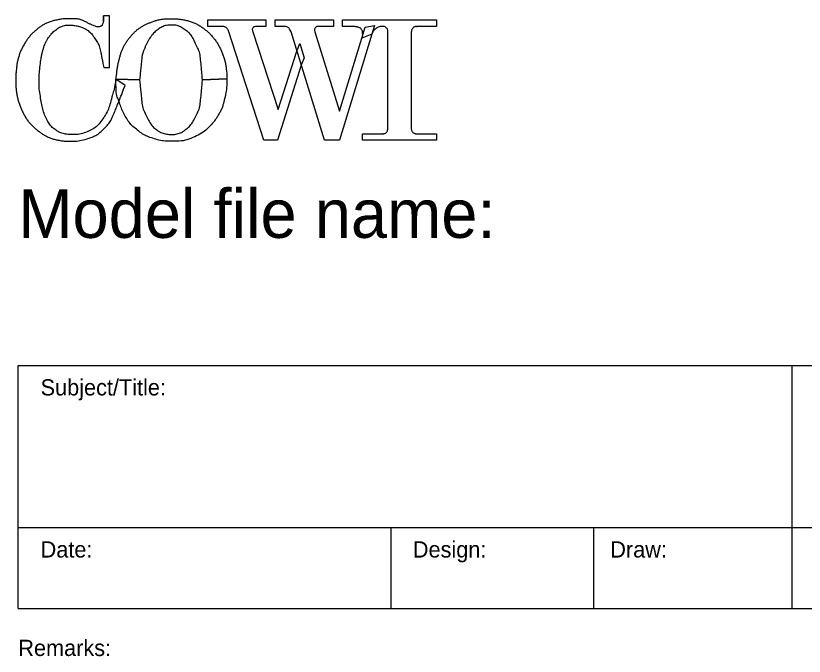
# Model space of a CAD drawing. Extents: x 0 to 511895, y 0 to 6211943.
# Drawn here: x -0.00016 to 0.04847, y -0.00294 to 0.03658 of the extents above; entities that cross this region are included whole.
import ezdxf

# ---------------------------------------------------------------- set-up
doc = ezdxf.new("R2010")
doc.units = 0
doc.layers.add('00_Modelskilt', color=7, linetype='Continuous')

msp = doc.modelspace()

# ---------------------------------------------------------------- linework, layer by layer
at = {"layer": '00_Modelskilt'}
for p, q in [((0.005244, 0.036576), (0.005244, 0.036326)), ((0.005624, 0.036576), (0.005244, 0.036576)), ((0.005244, 0.036576), (0.005244, 0.036226)), ((0.005244, 0.036226), (0.005244, 0.036576)), ((0.005244, 0.036576), (0.005244, 0.036326)), ((0.005624, 0.036576), (0.005244, 0.036576)), ((0.005244, 0.036576), (0.005244, 0.036226)), ((0.005244, 0.036226), (0.005244, 0.036576)), ((0.005624, 0.033376), (0.005624, 0.036576)), ((0.005624, 0.033376), (0.005624, 0.036576)), ((0.011694, 0.035916), (0.011694, 0.036326)), ((0.011694, 0.036326), (0.015274, 0.036326)), ((0.011694, 0.035916), (0.011694, 0.036326)), ((0.011694, 0.036326), (0.015274, 0.036326)), ((0.015274, 0.036326), (0.015274, 0.035916)), ((0.015274, 0.036326), (0.015274, 0.035916)), ((0.015834, 0.035916), (0.015834, 0.036326)), ((0.015834, 0.036326), (0.019434, 0.036326)), ((0.015834, 0.035916), (0.015834, 0.036326)), ((0.015834, 0.036326), (0.019434, 0.036326)), ((0.019434, 0.036326), (0.019434, 0.035916)), ((0.019434, 0.036326), (0.019434, 0.035916)), ((0.019994, 0.035916), (0.019994, 0.036326)), ((0.019994, 0.036326), (0.025784, 0.036326)), ((0.019994, 0.035916), (0.019994, 0.036326)), ((0.019994, 0.036326), (0.025784, 0.036326)), ((0.025784, 0.036326), (0.025784, 0.035916)), ((0.025784, 0.036326), (0.025784, 0.035916)), ((0.012504, 0.035916), (0.011694, 0.035916)), ((0.012504, 0.035916), (0.011694, 0.035916)), ((0.015144, 0.028906), (0.012994, 0.035586)), ((0.015144, 0.028906), (0.012994, 0.035586)), ((0.014464, 0.035586), (0.016034, 0.030786)), ((0.014464, 0.035586), (0.016034, 0.030786)), ((0.014714, 0.035916), (0.014634, 0.035906)), ((0.014714, 0.035916), (0.014634, 0.035906)), ((0.015274, 0.035916), (0.014714, 0.035916)), ((0.015274, 0.035916), (0.014714, 0.035916)), ((0.016344, 0.035916), (0.015834, 0.035916)), ((0.016344, 0.035916), (0.015834, 0.035916)), ((0.016384, 0.035916), (0.016344, 0.035916)), ((0.016384, 0.035916), (0.016344, 0.035916)), ((0.016824, 0.035586), (0.016774, 0.035686)), ((0.016824, 0.035586), (0.016774, 0.035686)), ((0.018874, 0.028906), (0.016824, 0.035586)), ((0.018874, 0.028906), (0.016824, 0.035586)), ((0.018274, 0.035696), (0.018294, 0.035586)), ((0.018274, 0.035696), (0.018294, 0.035586)), ((0.018294, 0.035586), (0.019814, 0.030686)), ((0.018294, 0.035586), (0.019814, 0.030686)), ((0.019434, 0.035916), (0.018574, 0.035916)), ((0.019434, 0.035916), (0.018574, 0.035916)), ((0.020654, 0.035916), (0.019994, 0.035916)), ((0.020654, 0.035916), (0.019994, 0.035916)), ((0.021194, 0.035186), (0.021394, 0.035866)), ((0.021194, 0.035186), (0.021394, 0.035866)), ((0.021394, 0.035866), (0.021964, 0.035966)), ((0.021394, 0.035866), (0.021964, 0.035966)), ((0.021964, 0.035966), (0.021794, 0.035436)), ((0.021964, 0.035966), (0.021794, 0.035436)), ((0.022784, 0.029696), (0.022784, 0.035536)), ((0.022784, 0.029696), (0.022784, 0.035536)), ((0.024234, 0.035536), (0.024234, 0.029696)), ((0.024234, 0.035536), (0.024234, 0.029696)), ((0.025784, 0.035916), (0.024564, 0.035906)), ((0.024564, 0.035906), (0.024594, 0.035916)), ((0.025784, 0.035916), (0.024564, 0.035906)), ((0.024564, 0.035906), (0.024594, 0.035916)), ((0.021794, 0.035436), (0.019814, 0.028906)), ((0.021794, 0.035436), (0.019814, 0.028906)), ((0.019814, 0.030686), (0.021194, 0.035186)), ((0.019814, 0.030686), (0.021194, 0.035186)), ((0.021794, 0.035436), (0.021194, 0.035186)), ((0.021794, 0.035436), (0.021194, 0.035186)), ((0.017174, 0.034396), (0.017364, 0.034866)), ((0.017174, 0.034396), (0.017364, 0.034866)), ((0.017364, 0.034866), (0.017624, 0.033976)), ((0.017364, 0.034866), (0.017624, 0.033976)), ((0.016034, 0.030786), (0.017174, 0.034396)), ((0.016034, 0.030786), (0.017174, 0.034396)), ((0.017624, 0.033976), (0.017454, 0.033526)), ((0.017624, 0.033976), (0.017454, 0.033526)), ((0.005274, 0.033376), (0.005624, 0.033376)), ((0.005274, 0.033376), (0.005624, 0.033376)), ((0.017454, 0.033526), (0.015984, 0.028906)), ((0.017454, 0.033526), (0.015984, 0.028906)), ((0.006584, 0.032266), (0.006014, 0.032656)), ((0.006014, 0.032656), (0.006014, 0.032616)), ((0.006044, 0.031866), (0.006014, 0.032656)), ((0.006014, 0.032656), (0.007484, 0.032616)), ((0.007484, 0.032616), (0.006014, 0.032656)), ((0.006014, 0.032656), (0.006014, 0.032616)), ((0.006584, 0.032266), (0.006014, 0.032656)), ((0.006014, 0.032656), (0.006014, 0.032616)), ((0.006044, 0.031866), (0.006014, 0.032656)), ((0.006014, 0.032656), (0.007484, 0.032616)), ((0.007484, 0.032616), (0.006014, 0.032656)), ((0.006014, 0.032656), (0.006014, 0.032616)), ((0.011364, 0.032616), (0.012864, 0.032676)), ((0.012864, 0.032676), (0.011364, 0.032616)), ((0.011364, 0.032616), (0.012864, 0.032676)), ((0.012864, 0.032676), (0.011364, 0.032616)), ((0.012864, 0.032676), (0.012864, 0.032616)), ((0.012864, 0.032676), (0.012864, 0.032616)), ((0.024234, 0.029696), (0.024234, 0.029606)), ((0.024234, 0.029696), (0.024234, 0.029606)), ((0.021234, 0.029286), (0.022474, 0.029296)), ((0.021234, 0.029286), (0.022474, 0.029296)), ((0.021234, 0.028906), (0.021234, 0.029286)), ((0.021234, 0.028906), (0.021234, 0.029286)), ((0.022474, 0.029296), (0.022454, 0.029286)), ((0.022474, 0.029296), (0.022454, 0.029286)), ((0.024594, 0.029286), (0.025784, 0.029286)), ((0.024594, 0.029286), (0.025784, 0.029286)), ((0.025784, 0.029286), (0.025784, 0.028906)), ((0.025784, 0.029286), (0.025784, 0.028906)), ((0.015984, 0.028906), (0.015144, 0.028906)), ((0.015984, 0.028906), (0.015144, 0.028906)), ((0.019814, 0.028906), (0.018874, 0.028906)), ((0.019814, 0.028906), (0.018874, 0.028906)), ((0.025784, 0.028906), (0.021234, 0.028906)), ((0.025784, 0.028906), (0.021234, 0.028906)), ((0, 0.015), (0.071, 0.015)), ((0, 0), (0, 0.015)), ((0.0477, 0.015), (0.0477, 0)), ((0, 0.005), (0.071, 0.005)), ((0.022975, 0.005), (0.022975, 0)), ((0.0355, 0), (0.0355, 0.005)), ((0, 0), (0.071, 0))]:
    msp.add_line(p, q, dxfattribs=at)
for points in [[(0.005244, 0.036326), (0.005244, 0.036232), (0.005233, 0.036139), (0.005194, 0.036046), (0.005166, 0.035982), (0.005108, 0.035939), (0.005044, 0.035916), (0.004963, 0.035888), (0.004872, 0.035888), (0.004794, 0.035916), (0.004683, 0.035956), (0.004573, 0.035999), (0.004464, 0.036046), (0.004281, 0.036125), (0.004117, 0.036224), (0.003924, 0.036296), (0.003691, 0.036384), (0.003451, 0.036395), (0.003214, 0.036396), (0.002954, 0.036398), (0.002693, 0.036375), (0.002434, 0.036326), (0.002195, 0.036281), (0.001968, 0.036218), (0.001744, 0.036116), (0.001539, 0.036023), (0.001359, 0.035906), (0.001184, 0.035766), (0.001007, 0.035626), (0.000848, 0.035479), (0.000704, 0.035306), (0.000557, 0.03513), (0.000435, 0.034946), (0.000324, 0.034746), (0.000211, 0.034543), (0.000113, 0.034338), (0.000044, 0.034116), (-0.000029, 0.033883), (-0.000077, 0.033648), (-0.000106, 0.033406), (-0.000138, 0.033143), (-0.000154, 0.03288), (-0.000156, 0.032616), (-0.000158, 0.032353), (-0.000145, 0.03209), (-0.000106, 0.031826), (-0.00007, 0.031583), (-0.000005, 0.03135), (0.000074, 0.031116), (0.000147, 0.030897), (0.000235, 0.03069), (0.000344, 0.030486), (0.000453, 0.030283), (0.000581, 0.0301), (0.000734, 0.029926), (0.000886, 0.029754), (0.001052, 0.029607), (0.001234, 0.029466), (0.001411, 0.02933), (0.00159, 0.029213), (0.001794, 0.029116), (0.002007, 0.029015), (0.002225, 0.028954), (0.002454, 0.028906), (0.002706, 0.028854), (0.002961, 0.028835), (0.003214, 0.028836), (0.003607, 0.028838), (0.003996, 0.028902), (0.004384, 0.029036), (0.004714, 0.02915), (0.004992, 0.029317), (0.005244, 0.029566), (0.005481, 0.029801), (0.005677, 0.030044), (0.005804, 0.030336), (0.005935, 0.030639), (0.006064, 0.03094), (0.006184, 0.031246), (0.006317, 0.031586), (0.006453, 0.031925), (0.006584, 0.032266)], [(0.005244, 0.036326), (0.005244, 0.036232), (0.005233, 0.036139), (0.005194, 0.036046), (0.005166, 0.035982), (0.005108, 0.035939), (0.005044, 0.035916), (0.004963, 0.035888), (0.004872, 0.035888), (0.004794, 0.035916), (0.004683, 0.035956), (0.004573, 0.035999), (0.004464, 0.036046), (0.004281, 0.036125), (0.004117, 0.036224), (0.003924, 0.036296), (0.003691, 0.036384), (0.003451, 0.036395), (0.003214, 0.036396), (0.002954, 0.036398), (0.002693, 0.036375), (0.002434, 0.036326), (0.002195, 0.036281), (0.001968, 0.036218), (0.001744, 0.036116), (0.001539, 0.036023), (0.001359, 0.035906), (0.001184, 0.035766), (0.001007, 0.035626), (0.000848, 0.035479), (0.000704, 0.035306), (0.000557, 0.03513), (0.000435, 0.034946), (0.000324, 0.034746), (0.000211, 0.034543), (0.000113, 0.034338), (0.000044, 0.034116), (-0.000029, 0.033883), (-0.000077, 0.033648), (-0.000106, 0.033406), (-0.000138, 0.033143), (-0.000154, 0.03288), (-0.000156, 0.032616), (-0.000158, 0.032353), (-0.000145, 0.03209), (-0.000106, 0.031826), (-0.00007, 0.031583), (-0.000005, 0.03135), (0.000074, 0.031116), (0.000147, 0.030897), (0.000235, 0.03069), (0.000344, 0.030486), (0.000453, 0.030283), (0.000581, 0.0301), (0.000734, 0.029926), (0.000886, 0.029754), (0.001052, 0.029607), (0.001234, 0.029466), (0.001411, 0.02933), (0.00159, 0.029213), (0.001794, 0.029116), (0.002007, 0.029015), (0.002225, 0.028954), (0.002454, 0.028906), (0.002706, 0.028854), (0.002961, 0.028835), (0.003214, 0.028836), (0.003607, 0.028838), (0.003996, 0.028902), (0.004384, 0.029036), (0.004714, 0.02915), (0.004992, 0.029317), (0.005244, 0.029566), (0.005481, 0.029801), (0.005677, 0.030044), (0.005804, 0.030336), (0.005935, 0.030639), (0.006064, 0.03094), (0.006184, 0.031246), (0.006317, 0.031586), (0.006453, 0.031925), (0.006584, 0.032266)], [(0.006014, 0.032616), (0.005936, 0.032136), (0.005806, 0.031668), (0.005674, 0.031196), (0.005566, 0.030811), (0.005387, 0.030467), (0.005144, 0.030126), (0.004931, 0.029828), (0.004674, 0.02962), (0.004334, 0.029466), (0.003962, 0.029298), (0.003589, 0.029235), (0.003214, 0.029246), (0.003064, 0.029251), (0.002914, 0.029274), (0.002764, 0.029316), (0.002617, 0.029358), (0.002484, 0.029407), (0.002354, 0.029496), (0.002082, 0.029684), (0.001884, 0.029914), (0.001744, 0.030206), (0.001577, 0.030556), (0.001476, 0.030905), (0.001414, 0.031276), (0.001339, 0.031723), (0.001274, 0.03217), (0.001284, 0.032616), (0.001294, 0.033066), (0.001341, 0.033516), (0.001414, 0.033966), (0.001446, 0.034164), (0.001487, 0.034355), (0.001544, 0.034546), (0.001593, 0.034714), (0.001662, 0.034871), (0.001744, 0.035026), (0.001822, 0.035175), (0.001915, 0.035308), (0.002024, 0.035436), (0.002122, 0.035552), (0.00223, 0.035646), (0.002354, 0.035736), (0.002482, 0.035829), (0.002613, 0.035898), (0.002764, 0.035946), (0.002912, 0.035994), (0.003065, 0.036005), (0.003214, 0.035996), (0.00349, 0.03598), (0.003764, 0.03593), (0.004034, 0.035816), (0.004155, 0.035765), (0.004255, 0.035701), (0.004354, 0.035616), (0.004463, 0.035523), (0.004553, 0.035424), (0.004634, 0.035306), (0.004809, 0.03505), (0.004982, 0.034793), (0.005044, 0.034496), (0.005121, 0.034123), (0.005196, 0.03375), (0.005274, 0.033376)], [(0.006014, 0.032616), (0.005936, 0.032136), (0.005806, 0.031668), (0.005674, 0.031196), (0.005566, 0.030811), (0.005387, 0.030467), (0.005144, 0.030126), (0.004931, 0.029828), (0.004674, 0.02962), (0.004334, 0.029466), (0.003962, 0.029298), (0.003589, 0.029235), (0.003214, 0.029246), (0.003064, 0.029251), (0.002914, 0.029274), (0.002764, 0.029316), (0.002617, 0.029358), (0.002484, 0.029407), (0.002354, 0.029496), (0.002082, 0.029684), (0.001884, 0.029914), (0.001744, 0.030206), (0.001577, 0.030556), (0.001476, 0.030905), (0.001414, 0.031276), (0.001339, 0.031723), (0.001274, 0.03217), (0.001284, 0.032616), (0.001294, 0.033066), (0.001341, 0.033516), (0.001414, 0.033966), (0.001446, 0.034164), (0.001487, 0.034355), (0.001544, 0.034546), (0.001593, 0.034714), (0.001662, 0.034871), (0.001744, 0.035026), (0.001822, 0.035175), (0.001915, 0.035308), (0.002024, 0.035436), (0.002122, 0.035552), (0.00223, 0.035646), (0.002354, 0.035736), (0.002482, 0.035829), (0.002613, 0.035898), (0.002764, 0.035946), (0.002912, 0.035994), (0.003065, 0.036005), (0.003214, 0.035996), (0.00349, 0.03598), (0.003764, 0.03593), (0.004034, 0.035816), (0.004155, 0.035765), (0.004255, 0.035701), (0.004354, 0.035616), (0.004463, 0.035523), (0.004553, 0.035424), (0.004634, 0.035306), (0.004809, 0.03505), (0.004982, 0.034793), (0.005044, 0.034496), (0.005121, 0.034123), (0.005196, 0.03375), (0.005274, 0.033376)], [(0.006014, 0.032616), (0.006054, 0.032869), (0.006076, 0.033123), (0.006114, 0.033376), (0.006147, 0.0336), (0.006205, 0.033817), (0.006264, 0.034036), (0.006315, 0.034229), (0.006379, 0.034415), (0.006464, 0.034596), (0.006553, 0.034787), (0.006669, 0.034957), (0.006794, 0.035126), (0.00691, 0.035284), (0.007032, 0.03543), (0.007174, 0.035566), (0.007314, 0.035702), (0.007465, 0.035817), (0.007634, 0.035916), (0.007805, 0.036017), (0.007979, 0.036096), (0.008164, 0.036166), (0.008364, 0.036243), (0.008563, 0.036307), (0.008774, 0.036346), (0.008994, 0.036388), (0.009214, 0.036398), (0.009434, 0.036396), (0.009687, 0.036394), (0.009941, 0.036371), (0.010194, 0.036326), (0.010433, 0.036284), (0.010659, 0.036216), (0.010884, 0.036116), (0.011094, 0.036023), (0.011282, 0.035907), (0.011464, 0.035766), (0.011644, 0.035627), (0.011804, 0.035478), (0.011954, 0.035306), (0.012107, 0.035131), (0.01224, 0.034949), (0.012354, 0.034746), (0.012468, 0.034543), (0.012559, 0.034336), (0.012634, 0.034116), (0.012713, 0.033883), (0.012782, 0.03365), (0.012814, 0.033406), (0.012845, 0.033163), (0.012867, 0.03292), (0.012864, 0.032676)], [(0.006014, 0.032616), (0.006054, 0.032869), (0.006076, 0.033123), (0.006114, 0.033376), (0.006147, 0.0336), (0.006205, 0.033817), (0.006264, 0.034036), (0.006315, 0.034229), (0.006379, 0.034415), (0.006464, 0.034596), (0.006553, 0.034787), (0.006669, 0.034957), (0.006794, 0.035126), (0.00691, 0.035284), (0.007032, 0.03543), (0.007174, 0.035566), (0.007314, 0.035702), (0.007465, 0.035817), (0.007634, 0.035916), (0.007805, 0.036017), (0.007979, 0.036096), (0.008164, 0.036166), (0.008364, 0.036243), (0.008563, 0.036307), (0.008774, 0.036346), (0.008994, 0.036388), (0.009214, 0.036398), (0.009434, 0.036396), (0.009687, 0.036394), (0.009941, 0.036371), (0.010194, 0.036326), (0.010433, 0.036284), (0.010659, 0.036216), (0.010884, 0.036116), (0.011094, 0.036023), (0.011282, 0.035907), (0.011464, 0.035766), (0.011644, 0.035627), (0.011804, 0.035478), (0.011954, 0.035306), (0.012107, 0.035131), (0.01224, 0.034949), (0.012354, 0.034746), (0.012468, 0.034543), (0.012559, 0.034336), (0.012634, 0.034116), (0.012713, 0.033883), (0.012782, 0.03365), (0.012814, 0.033406), (0.012845, 0.033163), (0.012867, 0.03292), (0.012864, 0.032676)], [(0.011364, 0.032616), (0.01132, 0.033066), (0.011278, 0.033516), (0.011234, 0.033966), (0.011197, 0.03434), (0.011014, 0.03468), (0.010854, 0.035026), (0.010785, 0.035174), (0.010712, 0.035312), (0.010604, 0.035436), (0.010498, 0.035558), (0.010375, 0.035645), (0.010244, 0.035736), (0.010122, 0.035821), (0.010008, 0.035898), (0.009864, 0.035946), (0.00972, 0.035995), (0.009577, 0.035996), (0.009434, 0.035996), (0.00929, 0.035996), (0.009147, 0.035992), (0.009004, 0.035946), (0.00886, 0.0359), (0.008743, 0.035826), (0.008624, 0.035736), (0.008502, 0.035645), (0.008391, 0.035553), (0.008294, 0.035436), (0.008186, 0.035307), (0.008095, 0.035172), (0.008014, 0.035026), (0.007926, 0.03487), (0.007849, 0.034713), (0.007784, 0.034546), (0.007709, 0.034357), (0.007633, 0.034167), (0.007614, 0.033966), (0.00757, 0.033516), (0.007527, 0.033066), (0.007484, 0.032616)], [(0.011364, 0.032616), (0.01132, 0.033066), (0.011278, 0.033516), (0.011234, 0.033966), (0.011197, 0.03434), (0.011014, 0.03468), (0.010854, 0.035026), (0.010785, 0.035174), (0.010712, 0.035312), (0.010604, 0.035436), (0.010498, 0.035558), (0.010375, 0.035645), (0.010244, 0.035736), (0.010122, 0.035821), (0.010008, 0.035898), (0.009864, 0.035946), (0.00972, 0.035995), (0.009577, 0.035996), (0.009434, 0.035996), (0.00929, 0.035996), (0.009147, 0.035992), (0.009004, 0.035946), (0.00886, 0.0359), (0.008743, 0.035826), (0.008624, 0.035736), (0.008502, 0.035645), (0.008391, 0.035553), (0.008294, 0.035436), (0.008186, 0.035307), (0.008095, 0.035172), (0.008014, 0.035026), (0.007926, 0.03487), (0.007849, 0.034713), (0.007784, 0.034546), (0.007709, 0.034357), (0.007633, 0.034167), (0.007614, 0.033966), (0.00757, 0.033516), (0.007527, 0.033066), (0.007484, 0.032616)], [(0.012994, 0.035586), (0.012976, 0.035627), (0.012955, 0.035667), (0.012934, 0.035706), (0.012904, 0.035761), (0.012869, 0.035808), (0.012814, 0.035846), (0.012745, 0.035894), (0.012671, 0.035911), (0.012594, 0.035916), (0.012564, 0.035918), (0.012534, 0.035914), (0.012504, 0.035916)], [(0.012994, 0.035586), (0.012976, 0.035627), (0.012955, 0.035667), (0.012934, 0.035706), (0.012904, 0.035761), (0.012869, 0.035808), (0.012814, 0.035846), (0.012745, 0.035894), (0.012671, 0.035911), (0.012594, 0.035916), (0.012564, 0.035918), (0.012534, 0.035914), (0.012504, 0.035916)], [(0.014634, 0.035906), (0.01458, 0.0359), (0.014529, 0.035897), (0.014484, 0.035846), (0.014429, 0.035786), (0.014431, 0.035719), (0.014444, 0.035656), (0.014449, 0.035633), (0.01446, 0.03561), (0.014464, 0.035586)], [(0.014634, 0.035906), (0.01458, 0.0359), (0.014529, 0.035897), (0.014484, 0.035846), (0.014429, 0.035786), (0.014431, 0.035719), (0.014444, 0.035656), (0.014449, 0.035633), (0.01446, 0.03561), (0.014464, 0.035586)], [(0.016774, 0.035686), (0.016743, 0.035748), (0.016707, 0.035804), (0.016644, 0.035846), (0.016562, 0.035901), (0.016474, 0.035916), (0.016384, 0.035916)], [(0.016774, 0.035686), (0.016743, 0.035748), (0.016707, 0.035804), (0.016644, 0.035846), (0.016562, 0.035901), (0.016474, 0.035916), (0.016384, 0.035916)], [(0.018574, 0.035916), (0.018541, 0.035914), (0.018507, 0.035919), (0.018474, 0.035916), (0.018419, 0.035913), (0.018369, 0.035896), (0.018324, 0.035846), (0.018281, 0.035798), (0.018264, 0.035748), (0.018274, 0.035696)], [(0.018574, 0.035916), (0.018541, 0.035914), (0.018507, 0.035919), (0.018474, 0.035916), (0.018419, 0.035913), (0.018369, 0.035896), (0.018324, 0.035846), (0.018281, 0.035798), (0.018264, 0.035748), (0.018274, 0.035696)], [(0.021194, 0.035186), (0.021206, 0.035243), (0.021221, 0.0353), (0.021234, 0.035356), (0.021245, 0.035405), (0.021238, 0.035456), (0.021234, 0.035506), (0.021227, 0.035586), (0.021217, 0.035663), (0.021164, 0.035736), (0.021111, 0.035809), (0.021041, 0.035844), (0.020964, 0.035866), (0.020901, 0.035885), (0.020838, 0.035901), (0.020774, 0.035906), (0.020734, 0.03591), (0.020694, 0.035913), (0.020654, 0.035916)], [(0.021194, 0.035186), (0.021206, 0.035243), (0.021221, 0.0353), (0.021234, 0.035356), (0.021245, 0.035405), (0.021238, 0.035456), (0.021234, 0.035506), (0.021227, 0.035586), (0.021217, 0.035663), (0.021164, 0.035736), (0.021111, 0.035809), (0.021041, 0.035844), (0.020964, 0.035866), (0.020901, 0.035885), (0.020838, 0.035901), (0.020774, 0.035906), (0.020734, 0.03591), (0.020694, 0.035913), (0.020654, 0.035916)], [(0.022784, 0.035536), (0.02278, 0.035563), (0.022785, 0.03559), (0.022784, 0.035616), (0.02278, 0.035687), (0.022778, 0.035753), (0.022714, 0.035816), (0.02263, 0.0359), (0.022542, 0.035919), (0.022454, 0.035916), (0.022321, 0.035913), (0.022183, 0.035881), (0.022054, 0.035786), (0.021975, 0.035729), (0.021927, 0.03567), (0.021884, 0.035596), (0.021852, 0.035543), (0.021821, 0.035491), (0.021794, 0.035436)], [(0.022784, 0.035536), (0.02278, 0.035563), (0.022785, 0.03559), (0.022784, 0.035616), (0.02278, 0.035687), (0.022778, 0.035753), (0.022714, 0.035816), (0.02263, 0.0359), (0.022542, 0.035919), (0.022454, 0.035916), (0.022321, 0.035913), (0.022183, 0.035881), (0.022054, 0.035786), (0.021975, 0.035729), (0.021927, 0.03567), (0.021884, 0.035596), (0.021852, 0.035543), (0.021821, 0.035491), (0.021794, 0.035436)], [(0.024594, 0.035916), (0.024557, 0.035913), (0.02452, 0.03591), (0.024484, 0.035906), (0.024426, 0.035901), (0.024375, 0.035866), (0.024334, 0.035816), (0.024282, 0.035754), (0.024257, 0.035689), (0.024244, 0.035616), (0.024239, 0.03559), (0.024235, 0.035563), (0.024234, 0.035536)], [(0.024594, 0.035916), (0.024557, 0.035913), (0.02452, 0.03591), (0.024484, 0.035906), (0.024426, 0.035901), (0.024375, 0.035866), (0.024334, 0.035816), (0.024282, 0.035754), (0.024257, 0.035689), (0.024244, 0.035616), (0.024239, 0.03559), (0.024235, 0.035563), (0.024234, 0.035536)], [(0.012864, 0.032616), (0.012864, 0.03211), (0.01277, 0.031612), (0.012634, 0.031116), (0.012572, 0.030891), (0.012469, 0.03069), (0.012354, 0.030486), (0.012239, 0.030283), (0.012111, 0.030104), (0.011954, 0.029926), (0.011647, 0.029581), (0.011321, 0.029316), (0.010884, 0.029116), (0.010403, 0.028896), (0.009919, 0.028833), (0.009434, 0.028836), (0.009055, 0.028839), (0.008673, 0.028889), (0.008294, 0.029016), (0.007944, 0.029134), (0.007645, 0.029287), (0.007354, 0.029516), (0.007063, 0.029746), (0.006824, 0.029992), (0.006644, 0.030306), (0.00646, 0.030627), (0.006324, 0.030952), (0.006204, 0.031296), (0.006138, 0.031485), (0.006051, 0.031669), (0.006044, 0.031866)], [(0.012864, 0.032616), (0.012864, 0.03211), (0.01277, 0.031612), (0.012634, 0.031116), (0.012572, 0.030891), (0.012469, 0.03069), (0.012354, 0.030486), (0.012239, 0.030283), (0.012111, 0.030104), (0.011954, 0.029926), (0.011647, 0.029581), (0.011321, 0.029316), (0.010884, 0.029116), (0.010403, 0.028896), (0.009919, 0.028833), (0.009434, 0.028836), (0.009055, 0.028839), (0.008673, 0.028889), (0.008294, 0.029016), (0.007944, 0.029134), (0.007645, 0.029287), (0.007354, 0.029516), (0.007063, 0.029746), (0.006824, 0.029992), (0.006644, 0.030306), (0.00646, 0.030627), (0.006324, 0.030952), (0.006204, 0.031296), (0.006138, 0.031485), (0.006051, 0.031669), (0.006044, 0.031866)], [(0.007484, 0.032616), (0.007527, 0.03217), (0.00757, 0.031723), (0.007614, 0.031276), (0.007651, 0.0309), (0.007812, 0.030554), (0.007994, 0.030206), (0.008143, 0.029921), (0.008326, 0.029685), (0.008594, 0.029496), (0.008723, 0.029405), (0.008856, 0.029357), (0.009004, 0.029316), (0.009147, 0.029277), (0.00929, 0.029248), (0.009434, 0.029246), (0.009577, 0.029245), (0.00972, 0.029274), (0.009864, 0.029316), (0.010002, 0.029357), (0.010124, 0.029409), (0.010244, 0.029496), (0.010509, 0.029691), (0.010701, 0.02992), (0.010854, 0.030206), (0.011039, 0.030553), (0.011197, 0.0309), (0.011234, 0.031276), (0.011277, 0.031723), (0.011321, 0.03217), (0.011364, 0.032616)], [(0.007484, 0.032616), (0.007527, 0.03217), (0.00757, 0.031723), (0.007614, 0.031276), (0.007651, 0.0309), (0.007812, 0.030554), (0.007994, 0.030206), (0.008143, 0.029921), (0.008326, 0.029685), (0.008594, 0.029496), (0.008723, 0.029405), (0.008856, 0.029357), (0.009004, 0.029316), (0.009147, 0.029277), (0.00929, 0.029248), (0.009434, 0.029246), (0.009577, 0.029245), (0.00972, 0.029274), (0.009864, 0.029316), (0.010002, 0.029357), (0.010124, 0.029409), (0.010244, 0.029496), (0.010509, 0.029691), (0.010701, 0.02992), (0.010854, 0.030206), (0.011039, 0.030553), (0.011197, 0.0309), (0.011234, 0.031276), (0.011277, 0.031723), (0.011321, 0.03217), (0.011364, 0.032616)], [(0.022454, 0.029286), (0.022481, 0.029287), (0.022507, 0.02929), (0.022534, 0.029296), (0.022608, 0.029313), (0.022673, 0.029349), (0.022724, 0.029416), (0.022767, 0.029473), (0.022781, 0.029533), (0.022784, 0.029596), (0.022785, 0.02963), (0.02278, 0.029663), (0.022784, 0.029696)], [(0.022454, 0.029286), (0.022481, 0.029287), (0.022507, 0.02929), (0.022534, 0.029296), (0.022608, 0.029313), (0.022673, 0.029349), (0.022724, 0.029416), (0.022767, 0.029473), (0.022781, 0.029533), (0.022784, 0.029596), (0.022785, 0.02963), (0.02278, 0.029663), (0.022784, 0.029696)], [(0.024234, 0.029606), (0.024234, 0.029535), (0.024261, 0.029468), (0.024314, 0.029406), (0.024362, 0.02935), (0.024419, 0.029322), (0.024484, 0.029306), (0.02452, 0.029298), (0.024557, 0.02929), (0.024594, 0.029286)], [(0.024234, 0.029606), (0.024234, 0.029535), (0.024261, 0.029468), (0.024314, 0.029406), (0.024362, 0.02935), (0.024419, 0.029322), (0.024484, 0.029306), (0.02452, 0.029298), (0.024557, 0.02929), (0.024594, 0.029286)]]:
    msp.add_open_spline(points, degree=3, dxfattribs=at)

# ---------------------------------------------------------------- texts
for s, height, p in [('Model file name:', 0.003, (0, 0.022873)), ('Subject/Title:', 0.001, (0.001375, 0.01315)), ('Date:', 0.001, (0.001375, 0.00315)), ('Design:', 0.001, (0.024335, 0.00315)), ('Draw:', 0.001, (0.036511, 0.00315)), ('Remarks:', 0.001, (0, -0.002925))]:
    msp.add_text(s, height=height, dxfattribs=at).set_placement(p)

doc.saveas('drawing.dxf')
